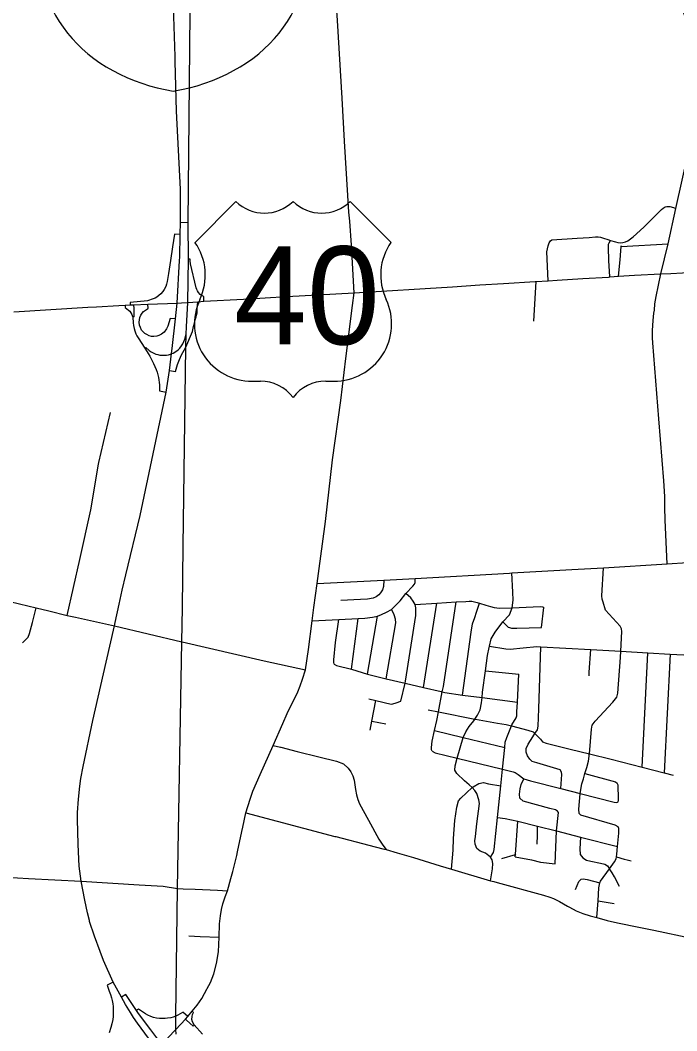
# Model space of a CAD drawing. Extents: x 1755200 to 1902939, y 644115 to 788070.
# Drawn here: x 1792682 to 1802010, y 701476 to 715838 of the extents above; entities that cross this region are included whole.
import ezdxf

# ---------------------------------------------------------------- set-up
doc = ezdxf.new("R2010")
doc.units = 0
for name, color, linetype in [('GM_X_City_Street', 7, 'Continuous'), ('GM_X_County_Road', 7, 'Continuous'), ('GM_X_Interchange_Ramps', 7, 'Continuous'), ('GM_X_Interstate_Route', 7, 'Continuous'), ('GM_X_Interstate_Shield', 7, 'Continuous'), ('GM_X_Township', 7, 'Continuous'), ('GM_X_Township_Road', 7, 'Continuous'), ('GM_X_US_Route', 7, 'Continuous'), ('GM_X_US_Shield', 7, 'Continuous')]:
    doc.layers.add(name, color=color, linetype=linetype)

msp = doc.modelspace()

# ---------------------------------------------------------------- linework, layer by layer
at = {"layer": 'GM_X_City_Street'}
for points in [[(1801783, 712232), (1801888, 712660), (1801998, 713163), (1802166, 713923), (1802257, 714341), (1802307, 714574), (1802366, 714854), (1802375, 714963), (1802376, 715028), (1802376, 715110), (1802373, 715189), (1802351, 715313), (1802312, 715467), (1802267, 715593), (1802098, 715965), (1801849, 716524), (1801703, 716857), (1801227, 717912), (1800951, 718530), (1800949, 718535)], [(1800181, 712135), (1800162, 712548), (1800171, 712588), (1800182, 712632), (1800199, 712673), (1800216, 712700), (1800235, 712716), (1800597, 712742), (1800767, 712752), (1800853, 712757), (1800894, 712758), (1800927, 712754), (1800971, 712741), (1801028, 712722), (1801066, 712707), (1801139, 712686), (1801173, 712678), (1801208, 712676), (1801244, 712680), (1801280, 712688), (1801316, 712702), (1801389, 712761), (1801541, 712896), (1801776, 713127), (1801793, 713148), (1801816, 713168), (1801845, 713184), (1801867, 713191), (1801909, 713188), (1801961, 713175), (1801998, 713163)], [(1801058, 712190), (1801045, 712423), (1801038, 712608), (1801040, 712654), (1801048, 712676), (1801066, 712707)], [(1801221, 712621), (1801888, 712660)], [(1801183, 712198), (1801207, 712432), (1801217, 712558), (1801221, 712621), (1801224, 712634)], [(1800007, 712125), (1799974, 711563)], [(1801838, 709054), (1801838, 709068), (1801828, 709291), (1801753, 710172), (1801668, 711251), (1801666, 711324), (1801666, 711351)], [(1801874, 708112), (1801843, 708734), (1801838, 708918), (1801838, 709054)], [(1788515, 708542), (1789354, 708333), (1790016, 708175), (1790633, 708023), (1790901, 707956), (1791177, 707887), (1791463, 707818), (1791938, 707710), (1792555, 707570), (1792909, 707485), (1793091, 707442), (1793349, 707379), (1793470, 707354), (1794021, 707229), (1794980, 707005), (1794985, 707004)], [(1796903, 707833), (1796938, 708115), (1796943, 708150)], [(1799635, 707981), (1799666, 707983), (1800517, 708032), (1800969, 708055), (1801874, 708112), (1802160, 708130), (1802839, 708170)], [(1800765, 705387), (1800766, 705396), (1800768, 705412), (1800796, 705762), (1800810, 705818), (1800849, 705876), (1801102, 706145), (1801156, 706216), (1801171, 706272), (1801208, 706781), (1801213, 706869), (1801227, 707152), (1801223, 707189), (1801205, 707225), (1800997, 707452), (1800966, 707565), (1800950, 707611), (1800943, 707657), (1800969, 708055)], [(1796903, 707833), (1797847, 707879), (1798294, 707904), (1799635, 707981)], [(1799486, 707218), (1799537, 707290), (1799635, 707388), (1799670, 707486), (1799687, 707596), (1799683, 707710), (1799666, 707983)], [(1795846, 704371), (1795888, 704574), (1795948, 704768), (1795988, 704882), (1796090, 705118), (1796277, 705531), (1796413, 705842), (1796476, 705983), (1796625, 706292), (1796660, 706376), (1796693, 706472), (1796735, 706604), (1796778, 706896), (1796831, 707300), (1796853, 707489), (1796903, 707833)], [(1796831, 707300), (1797208, 707322), (1797483, 707336), (1797580, 707341), (1797685, 707353), (1797759, 707369), (1797814, 707390), (1797887, 707423), (1797955, 707464), (1797994, 707500), (1798078, 707587), (1798160, 707691), (1798262, 707796), (1798286, 707821), (1798295, 707849), (1798294, 707904)], [(1797847, 707879), (1797845, 707792), (1797827, 707743), (1797800, 707698), (1797777, 707670), (1797741, 707643), (1797695, 707623), (1797617, 707612), (1797515, 707605), (1797236, 707591)], [(1798090, 706161), (1798152, 706416), (1798154, 706443), (1798304, 707376), (1798304, 707487), (1798294, 707535), (1798265, 707582), (1798232, 707630), (1798160, 707691)], [(1792716, 706990), (1792796, 707070), (1792816, 707121), (1792855, 707279), (1792909, 707485)], [(1798294, 707535), (1798599, 707552), (1798875, 707570), (1799013, 707579), (1799059, 707581), (1799100, 707580), (1799137, 707573), (1799173, 707564), (1799208, 707553), (1799296, 707523), (1799362, 707504), (1799417, 707493), (1799492, 707483), (1799670, 707486), (1800067, 707507), (1800108, 707501), (1800122, 707492)], [(1798411, 706355), (1798599, 707552)], [(1798534, 705449), (1798526, 705469), (1798524, 705503), (1798537, 705594), (1798569, 705742), (1798599, 705884), (1798625, 706009), (1798679, 706291), (1798696, 706370), (1798875, 707570)], [(1798968, 706246), (1799088, 707140), (1799109, 707259), (1799141, 707349), (1799164, 707423), (1799208, 707553)], [(1800088, 707205), (1800122, 707492)], [(1797391, 706614), (1797483, 707336)], [(1797618, 706542), (1797759, 707369)], [(1797881, 706479), (1798020, 707273), (1798015, 707325), (1797997, 707389), (1797976, 707430), (1797955, 707464)], [(1797144, 706688), (1797137, 706714), (1797136, 706748), (1797163, 706994), (1797208, 707322)], [(1799349, 706942), (1799375, 707045), (1799429, 707139), (1799483, 707214), (1799486, 707218)], [(1799537, 707290), (1799615, 707214), (1799635, 707208), (1799661, 707200), (1799737, 707199), (1800088, 707205)], [(1794985, 707004), (1796150, 706735), (1796735, 706604)], [(1799365, 703606), (1799394, 703779), (1799398, 703853), (1799385, 703905), (1799364, 703941), (1799292, 704000), (1799218, 704029), (1799169, 704068), (1799147, 704128), (1799141, 704176), (1799148, 704238), (1799167, 704415), (1799205, 704704), (1799197, 704759), (1799168, 704849), (1799142, 704891), (1799101, 704931), (1799061, 704971), (1798992, 705026), (1798883, 705130), (1798855, 705180), (1798863, 705241), (1798892, 705348), (1798973, 705645), (1799012, 705726), (1799061, 705802), (1799125, 705879), (1799142, 705905), (1799178, 705960), (1799216, 706038), (1799237, 706137), (1799245, 706211), (1799252, 706286), (1799291, 706593), (1799319, 706810), (1799344, 706922), (1799349, 706942)], [(1799349, 706942), (1799579, 706903), (1799645, 706901), (1799829, 706917), (1800024, 706936), (1800078, 706930), (1800788, 706894), (1801213, 706869), (1801599, 706846), (1801918, 706827), (1802203, 706814), (1802524, 706801), (1802826, 706788), (1803093, 706776)], [(1800363, 704917), (1800377, 705118), (1800373, 705152), (1800355, 705182), (1800023, 705282), (1799957, 705304), (1799921, 705336), (1799888, 705382), (1799870, 705436), (1799869, 705488), (1799899, 705549), (1799965, 705654), (1799994, 705699), (1800030, 705754), (1800042, 705805), (1800048, 706052), (1800078, 706930)], [(1800766, 706574), (1800766, 706574), (1800788, 706894)], [(1801516, 705223), (1801599, 706846)], [(1801918, 706827), (1801831, 705143)], [(1797144, 706688), (1797178, 706667), (1797391, 706614), (1797618, 706542), (1797881, 706479), (1798152, 706416), (1798411, 706355), (1798661, 706296), (1798679, 706291), (1798715, 706282), (1798968, 706246), (1799245, 706211), (1799745, 706148)], [(1799291, 706593), (1799766, 706542)], [(1799364, 703941), (1799407, 704011), (1799416, 704053), (1799463, 704507), (1799510, 704956), (1799534, 705193), (1799567, 705503), (1799574, 705577), (1799596, 705643), (1799661, 705809), (1799667, 705824), (1799726, 705921), (1799738, 705953), (1799737, 706010), (1799745, 706148), (1799766, 706542)], [(1800763, 706521), (1800766, 706574)], [(1797633, 706194), (1797735, 706169), (1797950, 706116), (1797974, 706120), (1798022, 706137), (1798090, 706161)], [(1797652, 705749), (1797677, 705874), (1797735, 706169)], [(1798476, 706039), (1798625, 706009), (1799142, 705905), (1799149, 705903), (1799462, 705849), (1799588, 705828), (1799661, 705809), (1799894, 705748), (1799968, 705724), (1799994, 705699), (1800017, 705678), (1800075, 705618), (1800101, 705584), (1800152, 705562), (1800497, 705478), (1800768, 705412), (1801076, 705336), (1801516, 705223), (1801831, 705143), (1801959, 705110)], [(1797677, 705874), (1797876, 705837)], [(1798569, 705742), (1798973, 705645), (1799567, 705503)], [(1796277, 705531), (1796379, 705506)], [(1798534, 705449), (1798575, 705425), (1798892, 705348), (1799534, 705193), (1799551, 705189), (1799687, 705156), (1799713, 705148), (1799756, 705120), (1799837, 705056), (1799931, 705027), (1800363, 704917), (1800639, 704846), (1801122, 704723), (1801156, 704720), (1801178, 704728), (1801182, 704748), (1801182, 704772), (1801178, 704967), (1801162, 704995)], [(1800875, 703085), (1800893, 703323), (1800904, 703509), (1800910, 703555), (1800919, 703580), (1800927, 703601), (1801053, 703776), (1801126, 703878), (1801148, 703918), (1801152, 703949), (1801157, 703986), (1801168, 704097), (1801187, 704284), (1801185, 704350), (1801179, 704374), (1801136, 704398), (1800646, 704541), (1800624, 704563), (1800617, 704624), (1800638, 704843), (1800639, 704846), (1800663, 704983), (1800685, 705056), (1800705, 705130), (1800730, 705217), (1800755, 705307), (1800764, 705380), (1800765, 705387)], [(1800280, 703850), (1800299, 704316), (1800329, 704579), (1800313, 704597), (1800285, 704617), (1800208, 704637), (1799827, 704739), (1799780, 704781), (1799774, 704839), (1799783, 704915), (1799801, 704978), (1799837, 705056)], [(1800705, 705130), (1801140, 705013), (1801162, 704995)], [(1798808, 703772), (1798833, 704043), (1798840, 704208), (1798858, 704463), (1798883, 704652), (1798908, 704743), (1798944, 704783), (1799101, 704931), (1799115, 704945), (1799199, 704992), (1799263, 705002), (1799334, 704987), (1799510, 704956)], [(1795888, 704574), (1797152, 704239), (1797168, 704235)], [(1799463, 704507), (1799574, 704492), (1799752, 704454), (1800031, 704383), (1800299, 704316), (1800644, 704229), (1801168, 704097)], [(1795771, 704017), (1795833, 704307), (1795846, 704371)], [(1799714, 703950), (1799717, 703982), (1799752, 704454)], [(1800029, 704254), (1800029, 704254), (1800031, 704383)], [(1797168, 704235), (1797635, 704116), (1797835, 704062)], [(1800027, 704126), (1800029, 704254)], [(1800644, 704229), (1800631, 704061), (1800638, 703983), (1800674, 703933), (1800725, 703901), (1800789, 703884), (1800928, 703860), (1800990, 703845), (1801024, 703819), (1801053, 703776)], [(1787779, 703998), (1787960, 703973), (1788286, 703945), (1788959, 703862), (1789488, 703824), (1792326, 703669), (1792799, 703642)], [(1795333, 702066), (1795340, 702078), (1795387, 702164), (1795433, 702283), (1795470, 702432), (1795501, 702597), (1795508, 702805), (1795515, 702995), (1795528, 703110), (1795544, 703200), (1795563, 703281), (1795593, 703378), (1795625, 703467), (1795676, 703640), (1795704, 703739), (1795761, 703969), (1795771, 704017)], [(1799525, 703925), (1799717, 703982), (1799724, 703984)], [(1799714, 703950), (1799945, 703904), (1800073, 703871), (1800280, 703850)], [(1801152, 703949), (1801264, 703915), (1801306, 703903), (1801362, 703891)], [(1798647, 703822), (1798808, 703772), (1799365, 703606), (1799409, 703595)], [(1801195, 703525), (1801123, 703665), (1801093, 703721), (1801053, 703776)], [(1792799, 703642), (1793175, 703621), (1793549, 703604), (1794370, 703551)], [(1800573, 703485), (1800619, 703595), (1800650, 703630), (1800680, 703636), (1800735, 703628), (1800919, 703580)], [(1794370, 703551), (1794714, 703529), (1794915, 703497), (1794996, 703494)], [(1794996, 703494), (1795167, 703487), (1795486, 703473), (1795625, 703467)], [(1800893, 703323), (1801122, 703283)], [(1800459, 703246), (1800484, 703232), (1800580, 703181), (1800676, 703143), (1800777, 703111), (1800875, 703085), (1801022, 703044), (1801169, 703009), (1801472, 702946), (1801685, 702904), (1802220, 702791), (1802629, 702690), (1802804, 702646), (1802914, 702611), (1803280, 702499), (1803315, 702487)], [(1795080, 702826), (1795238, 702814), (1795508, 702805)], [(1793741, 700437), (1793752, 700441), (1793845, 700487), (1793927, 700535), (1794011, 700592), (1794134, 700688), (1794214, 700764), (1794240, 700797), (1794396, 700960), (1794557, 701136), (1794621, 701208), (1794693, 701283), (1794864, 701465), (1794893, 701495), (1795030, 701641), (1795063, 701678), (1795126, 701755), (1795195, 701840), (1795261, 701935), (1795301, 702007), (1795333, 702066)]]:
    msp.add_lwpolyline(points, dxfattribs=at)
at = {"layer": 'GM_X_County_Road'}
for points in [[(1797189, 715833), (1797177, 716035), (1797112, 716868), (1797075, 717769)], [(1797353, 713112), (1797336, 713346), (1797291, 714121), (1797254, 714730), (1797189, 715833)], [(1797426, 711962), (1797426, 711962), (1797388, 712641), (1797363, 712981), (1797353, 713112)], [(1801691, 711717), (1801700, 711809), (1801717, 711912), (1801783, 712232)], [(1796943, 708150), (1797018, 708713), (1797121, 709588), (1797235, 710434), (1797309, 711031), (1797403, 711783), (1797426, 711962)], [(1801666, 711351), (1801666, 711428), (1801676, 711568), (1801686, 711673), (1801691, 711717)], [(1796379, 705506), (1796383, 705505), (1796617, 705443), (1796926, 705369), (1797174, 705307), (1797274, 705270), (1797342, 705206), (1797381, 705156), (1797410, 705101), (1797429, 705036), (1797447, 704903), (1797458, 704829), (1797477, 704765), (1797501, 704699), (1797629, 704467), (1797779, 704200), (1797835, 704114), (1797879, 704050)], [(1797835, 704062), (1797879, 704050), (1798037, 704003), (1798269, 703938), (1798647, 703822)], [(1799409, 703595), (1799460, 703581)], [(1799460, 703581), (1800117, 703403), (1800206, 703377), (1800260, 703357), (1800343, 703314), (1800459, 703246)]]:
    msp.add_lwpolyline(points, dxfattribs=at)
at = {"layer": 'GM_X_Interchange_Ramps'}
for points in [[(1794451, 711176), (1794468, 711186), (1794516, 711144), (1794541, 711126), (1794563, 711113), (1794589, 711101), (1794609, 711093), (1794636, 711085), (1794665, 711079), (1794700, 711076), (1794731, 711076), (1794760, 711079), (1794787, 711084), (1794816, 711092), (1794833, 711099), (1794855, 711108), (1794891, 711129), (1794926, 711155), (1794950, 711179), (1794973, 711208), (1794994, 711240), (1795009, 711271), (1795021, 711305), (1795040, 711374), (1795044, 711478), (1795066, 711827), (1795073, 712442), (1795068, 712958), (1794961, 712962)], [(1794957, 712794), (1794873, 712797), (1794845, 712619), (1794816, 712421), (1794787, 712239), (1794771, 712124), (1794762, 712088), (1794749, 712053), (1794728, 712012), (1794708, 711983), (1794681, 711950), (1794653, 711925), (1794624, 711904), (1794600, 711889), (1794573, 711876), (1794493, 711851), (1794245, 711827), (1794246, 711792)], [(1795293, 711843), (1795289, 711911), (1795265, 711922), (1795239, 711941), (1795216, 711966), (1795200, 711991), (1795192, 712010), (1795184, 712033), (1795103, 712377), (1795098, 712419), (1795097, 712442), (1795073, 712442)], [(1794173, 711789), (1794175, 711754), (1794223, 711718), (1794240, 711701), (1794256, 711678), (1794268, 711656), (1794274, 711639), (1794280, 711619), (1794287, 711535), (1794291, 711499), (1794299, 711456), (1794309, 711424), (1794325, 711383), (1794339, 711354), (1794357, 711324), (1794451, 711176), (1794522, 711061), (1794577, 710959), (1794614, 710873), (1794627, 710835), (1794638, 710796), (1794647, 710760), (1794653, 710726), (1794658, 710690), (1794661, 710655), (1794663, 710623), (1794663, 710571), (1794758, 710551)], [(1794293, 711794), (1794296, 711740), (1794298, 711624), (1794280, 711619)], [(1794889, 711593), (1794811, 711598), (1794778, 711490), (1794762, 711451), (1794727, 711405), (1794690, 711375), (1794653, 711356), (1794621, 711347), (1794581, 711343), (1794547, 711345), (1794513, 711354), (1794479, 711369), (1794452, 711387), (1794428, 711409), (1794407, 711435), (1794389, 711469), (1794379, 711503), (1794373, 711546), (1794375, 711581), (1794384, 711614), (1794397, 711647), (1794416, 711676), (1794436, 711698), (1794460, 711718), (1794489, 711735), (1794498, 711739), (1794496, 711801)], [(1794805, 710858), (1794887, 710845), (1794916, 710943), (1794934, 710994), (1794968, 711071), (1795034, 711193), (1795128, 711412), (1795144, 711485), (1795158, 711532), (1795169, 711578), (1795182, 711621), (1795187, 711645), (1795195, 711678), (1795198, 711733), (1795203, 711781), (1795206, 711837)], [(1794003, 702169), (1793920, 702125), (1793947, 702039), (1793965, 701992), (1793980, 701944), (1793989, 701904), (1793997, 701861), (1794002, 701822), (1794005, 701768), (1794004, 701718), (1794002, 701681), (1793996, 701638), (1793984, 701575), (1793970, 701523), (1793946, 701449)], [(1794693, 701283), (1794540, 701490), (1794365, 701721), (1794336, 701764), (1794181, 701993), (1794119, 701955)], [(1795063, 701678), (1794992, 701738), (1794990, 701737), (1794957, 701716), (1794923, 701698), (1794894, 701685), (1794857, 701671), (1794822, 701661), (1794777, 701653), (1794740, 701649), (1794707, 701648), (1794659, 701651), (1794619, 701656), (1794576, 701666), (1794536, 701680), (1794494, 701698), (1794461, 701716), (1794363, 701783), (1794336, 701764)], [(1795273, 701426), (1795154, 701558), (1795131, 701601), (1795122, 701636), (1795123, 701678), (1795131, 701708), (1795145, 701737), (1795126, 701755)], [(1795154, 701558), (1795139, 701542), (1795047, 701625), (1795030, 701641)]]:
    msp.add_lwpolyline(points, dxfattribs=at)
at = {"layer": 'GM_X_Interstate_Route'}
for points in [[(1794885, 715265), (1794883, 715320), (1794853, 716180), (1794855, 716550)], [(1794960, 713284), (1794960, 713438), (1794905, 714544), (1794885, 715252), (1794885, 715265)], [(1794957, 712794), (1794961, 712962), (1794960, 713284)], [(1794949, 712468), (1794957, 712794)], [(1794910, 711817), (1794947, 712424), (1794949, 712468)], [(1794841, 711173), (1794889, 711593), (1794910, 711817)], [(1794133, 707740), (1794184, 707954), (1794386, 708797), (1794758, 710551), (1794805, 710858), (1794833, 711099), (1794841, 711173)], [(1794032, 707280), (1794086, 707538), (1794133, 707740)], [(1793904, 706716), (1794021, 707229), (1794032, 707280)], [(1793505, 704128), (1793494, 704479), (1793497, 704580), (1793509, 704767), (1793528, 704952), (1793543, 705063), (1793577, 705232), (1793714, 705887), (1793904, 706716)], [(1793549, 703604), (1793522, 703813), (1793509, 704020), (1793505, 704128)], [(1793666, 703043), (1793638, 703152), (1793600, 703331), (1793549, 703604)], [(1794293, 701666), (1794247, 701734), (1794180, 701849), (1794119, 701955), (1794003, 702169), (1793864, 702475), (1793816, 702601), (1793736, 702820), (1793669, 703029), (1793666, 703043)], [(1794621, 701208), (1794347, 701585), (1794293, 701666)]]:
    msp.add_lwpolyline(points, dxfattribs=at)
at = {"layer": 'GM_X_Interstate_Shield'}
for centre, start_param, end_param in [((1795326, 716667), 2.911027, 4.511031), ((1794388, 716667), 4.913747, 6.513751)]:
    msp.add_ellipse(centre, major_axis=(2344, 0), ratio=0.8, start_param=start_param, end_param=end_param, dxfattribs=at)
at = {"layer": 'GM_X_Township'}
msp.add_lwpolyline([(1794896, 701429), (1794893, 701495), (1794894, 701685), (1794915, 703497), (1794980, 707005), (1794986, 707486), (1794997, 708362), (1795034, 711193), (1795040, 711374), (1795044, 711478), (1795066, 711827), (1795073, 712442), (1795068, 712958), (1795095, 715947)], dxfattribs=at)
at = {"layer": 'GM_X_Township_Road'}
msp.add_lwpolyline([(1793349, 707379), (1793530, 708174), (1793686, 708880), (1793794, 709528), (1793800, 709554), (1793964, 710261)], dxfattribs=at)
at = {"layer": 'GM_X_US_Route'}
for points in [[(1799996, 712124), (1800007, 712125), (1800181, 712135), (1800311, 712142), (1800675, 712165), (1801038, 712188), (1801058, 712190), (1801183, 712198), (1801409, 712213), (1801783, 712232), (1801925, 712239)], [(1801925, 712239), (1802256, 712256)], [(1798823, 712050), (1799214, 712075)], [(1799214, 712075), (1799549, 712096)], [(1799549, 712096), (1799996, 712124)], [(1796472, 711909), (1797426, 711962)], [(1797426, 711962), (1798823, 712050)], [(1793765, 711765), (1794082, 711781), (1794173, 711789)], [(1794173, 711789), (1794246, 711792), (1794293, 711794), (1794496, 711801), (1794910, 711817)], [(1794910, 711817), (1794976, 711821)], [(1794976, 711821), (1795066, 711827), (1795206, 711837)], [(1795206, 711837), (1795293, 711843)], [(1795293, 711843), (1795293, 711843), (1795855, 711874)], [(1795855, 711874), (1796472, 711909)], [(1792592, 711694), (1793645, 711758), (1793765, 711765)]]:
    msp.add_lwpolyline(points, dxfattribs=at)
at = {"layer": 'GM_X_US_Shield'}
for p, q in [((1795746, 713261), (1795166, 712681)), ((1797950, 712681), (1797370, 713261)), ((1795978, 710709), (1796094, 710709)), ((1797022, 710709), (1797138, 710709))]:
    msp.add_line(p, q, dxfattribs=at)
for centre, radius, start, end in [((1796152, 713676), 580, 225.573, 314.427), ((1796964, 713676), 580, 225.573, 314.427), ((1794500, 712215), 812, 334.5471, 35.0009), ((1798615, 712215), 812, 144.9991, 205.4529), ((1795969, 711521), 812, 154.8319, 270.6383), ((1797147, 711521), 812, 269.3617, 25.1681), ((1796094, 710129), 580, 36.8699, 90), ((1797022, 710129), 580, 90, 143.1301)]:
    msp.add_arc(centre, radius, start, end, dxfattribs=at)

# ---------------------------------------------------------------- texts
msp.add_text('40', height=1392.2, dxfattribs=at).set_placement((1795721, 711231))

doc.saveas('drawing.dxf')
